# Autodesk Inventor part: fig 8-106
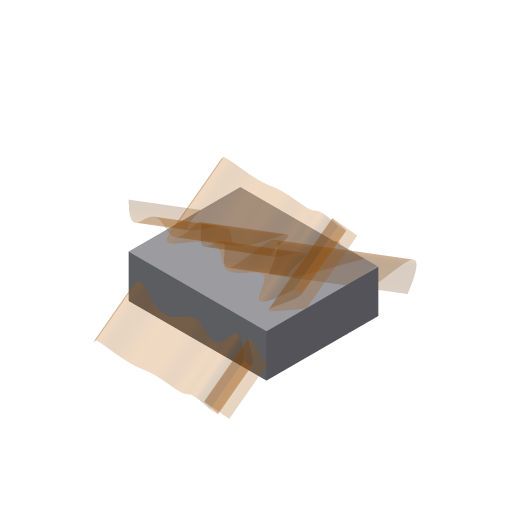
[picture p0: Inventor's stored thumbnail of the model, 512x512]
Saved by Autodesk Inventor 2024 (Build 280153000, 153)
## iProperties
Shininess: 64.0
Length Units: 11269
Angle Units: 11279
Time Units: 11290
Mass Units: 11283
Length Display Precision: 3
Angle Display Precision: 2
Compacted: True
Part Number: fig 8-106
Document SubType Name: Modeling
Created: 2002-12
Designer: deepak
Density: 1 g/cm^3
Material: Generic
Appearance: Default
Density: 0.0
Volumn: 0.0
Area: 0.0
PropertySet Name: Model Information
Control State: 0
Master: False
Checked Out: False
Author: deepak
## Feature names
1. Extrusion1
## Parameters: d1 = 0, d2 = 0, d3 = 0, d4 = 0, d5 = 0
